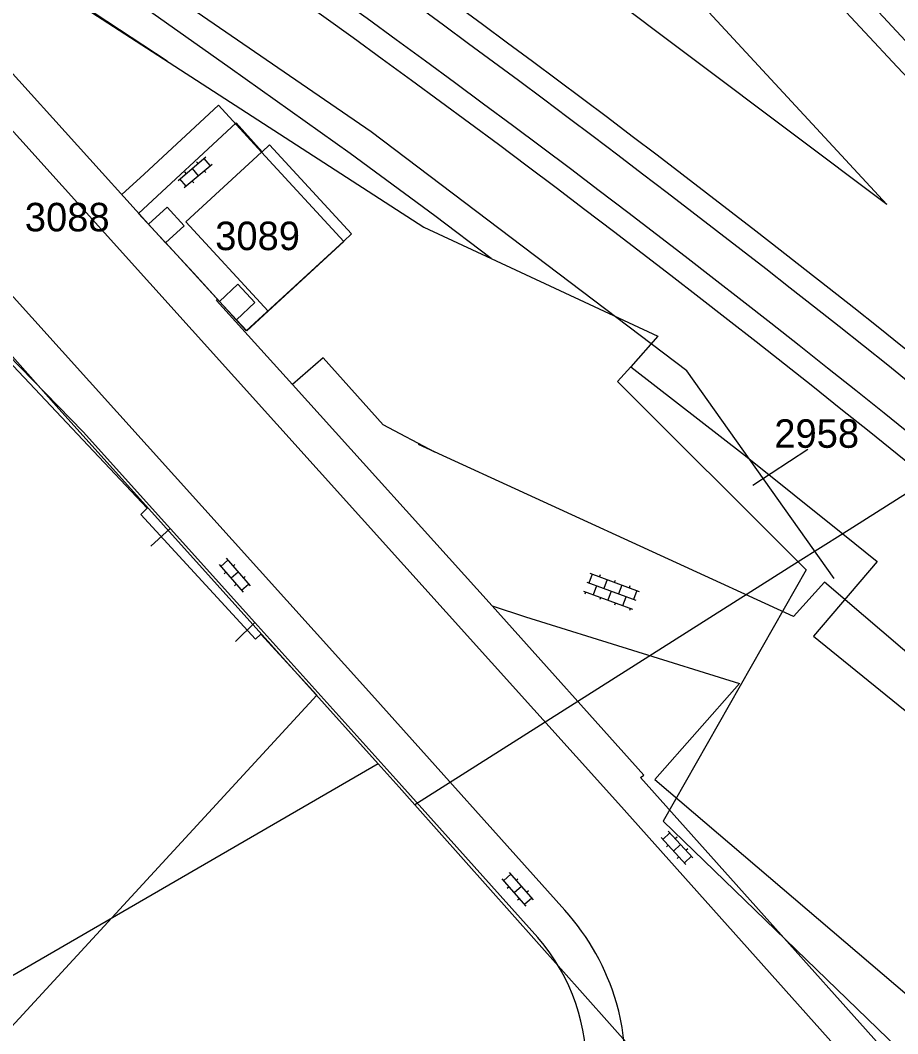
# Model space of a CAD drawing. Extents: x 148816 to 151297, y 399515 to 402500.
# Drawn here: x 149846 to 149901.4, y 399838.3 to 399902.3 of the extents above; entities that cross this region are included whole.
import ezdxf

# ---------------------------------------------------------------- set-up
doc = ezdxf.new("R2010")
doc.units = 0
for name, color, linetype in [('B01 Hoofdgebouw  [T] Norm', 7, 'Continuous'), ('B01 hoofgebouw', 7, 'Continuous'), ('G01 perceelsgrens', 7, 'Continuous'), ('Q01 Spoorrail  [D] Norm', 7, 'Continuous'), ('Q19 Overig lijnvormig object  [D] Gem', 7, 'Continuous'), ('S02 Open verharding  Norm', 7, 'Continuous'), ('T01 Muur  [T] Gem', 7, 'Continuous'), ('T04 Haag heg  [D] Gem', 7, 'Continuous'), ('V00 Kant verharding algemeen  [T] Norm', 7, 'Continuous'), ('Z01 perceelnummer', 7, 'Continuous')]:
    doc.layers.add(name, color=color, linetype=linetype)

msp = doc.modelspace()

# ---------------------------------------------------------------- linework, layer by layer
at = {"layer": 'B01 Hoofdgebouw  [T] Norm'}
msp.add_lwpolyline([(149866.456, 399888.377), (149861.68, 399883.975), (149856.48, 399889.615), (149861.256, 399894.018), (149866.456, 399888.377)], dxfattribs=at)
at = {"layer": 'B01 hoofgebouw'}
msp.add_lwpolyline([(149866.456, 399888.377), (149861.68, 399883.975), (149856.48, 399889.615), (149861.256, 399894.018), (149866.456, 399888.377)], dxfattribs=at)
at = {"layer": 'G01 perceelsgrens'}
for points in [[(149824.935, 399971.333), (149852.884, 399942.282), (149864.818, 399929.5), (149871.974, 399921.819), (149900.742, 399890.705), (149870.334, 399913.557), (149853.477, 399925.258), (149834.506, 399937.866), (149821.784, 399945.874), (149804.582, 399956.252), (149802.467, 399957.457)], [(149875.758, 399887.296), (149872.208, 399889.988), (149866.85, 399893.936), (149859.277, 399899.32), (149850.004, 399905.879), (149836.582, 399915.04), (149825.092, 399922.506), (149814.909, 399928.886), (149808.684, 399932.764), (149798.2, 399939.123), (149791.397, 399943.069)], [(149790.081, 399941.851), (149797.325, 399937.507), (149811.909, 399927.963), (149828.421, 399917.246), (149849.831, 399903.3), (149871.509, 399889.277), (149875.758, 399887.296)], [(149859.646, 399895.855), (149853.492, 399890.143)], [(149861.3, 399894.039), (149859.646, 399895.855)], [(149861.753, 399894.468), (149861.3, 399894.039)], [(149866.933, 399888.848), (149861.753, 399894.468)], [(149853.492, 399890.143), (149856.962, 399886.385)], [(149929.95, 399890.177), (149897.953, 399869.91)], [(149860.287, 399882.727), (149866.453, 399888.385)], [(149866.453, 399888.385), (149866.933, 399888.848)], [(149875.758, 399887.296), (149886.287, 399882.387), (149884.567, 399880.454)], [(149856.962, 399886.385), (149860.287, 399882.727)], [(149868.617, 399855.387), (149848.283, 399877.988), (149844.198, 399882.585)], [(149884.567, 399880.454), (149883.742, 399879.528), (149895.151, 399868.135)], [(149884.567, 399880.454), (149891.806, 399874.825), (149897.953, 399869.91)], [(149897.953, 399869.91), (149895.151, 399868.135)], [(149897.953, 399869.91), (149900.131, 399868.169), (149896.12, 399863.44), (149908.811, 399853.147), (149904.399, 399847.754), (149925.296, 399829.361), (149938.329, 399818.136), (149945.279, 399811.233), (149959.753, 399797.315), (149974.114, 399782.577), (149983.256, 399773.23), (149993.692, 399761.304), (150000, 399754.699)], [(149895.151, 399868.135), (149870.937, 399852.797)], [(149895.151, 399868.135), (149895.651, 399867.636), (149886.613, 399851.775), (149902.731, 399836.159), (149928.371, 399811.629), (149934.035, 399805.696), (149933.719, 399805.421)], [(149868.617, 399855.387), (149834.908, 399835.857), (149834.289, 399833.183)], [(149870.937, 399852.797), (149869.945, 399853.91), (149868.617, 399855.387)], [(149957.351, 399719.887), (149956.41, 399721.331), (149950.17, 399730.991), (149946.258, 399736.942), (149943.568, 399741.016), (149939.872, 399747.868), (149932.064, 399762.587), (149924.088, 399777.479), (149924.56, 399777.709), (149921.456, 399787.322), (149922.054, 399787.507), (149916.585, 399805.472), (149903.205, 399816.56), (149870.937, 399852.797)]]:
    msp.add_lwpolyline(points, dxfattribs=at)
at = {"layer": 'Q01 Spoorrail  [D] Norm'}
for p, q in [((149887.692, 399916.316), (149902.498, 399900.422)), ((149886.594, 399915.294), (149901.4, 399899.4)), ((149901.4, 399899.4), (149918.82, 399880.701))]:
    msp.add_line(p, q, dxfattribs=at)
for centre, radius, start, end in [((149374.899, 399222.566), 839.824, 47.976611, 67.901486), ((149374.91, 399222.59), 843.799, 50.163417, 67.241111), ((149374.899, 399222.566), 838.324, 47.976611, 67.901486), ((149374.91, 399222.59), 842.299, 50.163417, 67.241111), ((151998.933, 402054.677), 2999.25, 225.295789, 226.202153), ((151998.933, 402054.677), 3000.75, 225.295789, 226.202153)]:
    msp.add_arc(centre, radius, start, end, dxfattribs=at)
at = {"layer": 'Q19 Overig lijnvormig object  [D] Gem'}
for points in [[(149856.377, 399889.35), (149855.199, 399888.282), (149854.127, 399889.465), (149855.305, 399890.533), (149856.377, 399889.35)], [(149859.762, 399885.667), (149860.835, 399884.513), (149859.67, 399883.431), (149858.598, 399884.584), (149859.762, 399885.667)]]:
    msp.add_lwpolyline(points, dxfattribs=at)
at = {"layer": 'S02 Open verharding  Norm'}
for p, q in [((149855.992, 399892.227), (149857.748, 399893.713)), ((149857.155, 399893.407), (149857.252, 399893.293)), ((149858.021, 399893.158), (149857.634, 399893.616)), ((149856.38, 399891.769), (149858.136, 399893.255)), ((149856.392, 399892.762), (149856.489, 399892.647)), ((149856.87, 399892.97), (149857.258, 399892.512)), ((149857.639, 399892.835), (149857.736, 399892.72)), ((149856.494, 399891.866), (149856.107, 399892.324)), ((149856.876, 399892.189), (149856.973, 399892.075)), ((149858.579, 399867.97), (149860.086, 399866.233)), ((149858.677, 399867.857), (149859.13, 399868.25)), ((149859.032, 399868.363), (149860.539, 399866.626)), ((149859.571, 399867.971), (149859.458, 399867.872)), ((149859.005, 399867.479), (149858.891, 399867.381)), ((149859.786, 399867.495), (149859.332, 399867.101)), ((149860.227, 399867.215), (149860.113, 399867.117)), ((149882.138, 399867.366), (149881.93, 399866.803)), ((149881.997, 399867.418), (149885.094, 399866.278)), ((149882.607, 399867.194), (149882.659, 399867.334)), ((149859.66, 399866.724), (149859.547, 399866.625)), ((149859.988, 399866.346), (149860.441, 399866.739)), ((149881.79, 399866.855), (149884.886, 399865.715)), ((149882.4, 399866.631), (149882.192, 399866.068)), ((149883.076, 399867.021), (149882.869, 399866.458)), ((149883.545, 399866.848), (149883.597, 399866.989)), ((149884.015, 399866.675), (149883.807, 399866.112)), ((149884.484, 399866.502), (149884.536, 399866.643)), ((149881.582, 399866.292), (149884.679, 399865.152)), ((149881.723, 399866.24), (149881.671, 399866.1)), ((149882.661, 399865.895), (149882.61, 399865.754)), ((149883.338, 399866.285), (149883.131, 399865.722)), ((149884.069, 399865.376), (149884.276, 399865.939)), ((149884.953, 399866.33), (149884.746, 399865.767)), ((149883.6, 399865.549), (149883.548, 399865.408)), ((149884.538, 399865.204), (149884.486, 399865.063)), ((149886.941, 399851.134), (149888.498, 399849.441)), ((149886.5, 399850.727), (149888.057, 399849.034)), ((149886.601, 399850.617), (149887.043, 399851.023)), ((149887.492, 399850.757), (149887.381, 399850.655)), ((149886.94, 399850.249), (149886.829, 399850.147)), ((149887.72, 399850.287), (149887.278, 399849.881)), ((149888.169, 399850.021), (149888.058, 399849.919)), ((149887.617, 399849.513), (149887.506, 399849.411)), ((149887.955, 399849.145), (149888.397, 399849.551)), ((149877.97, 399846.399), (149876.455, 399848.129)), ((149877.005, 399848.412), (149876.553, 399848.017)), ((149878.421, 399846.795), (149876.906, 399848.525)), ((149877.334, 399848.036), (149877.447, 399848.135)), ((149876.77, 399847.542), (149876.883, 399847.64)), ((149877.212, 399847.264), (149877.664, 399847.66)), ((149877.993, 399847.284), (149878.106, 399847.382)), ((149877.429, 399846.789), (149877.542, 399846.888)), ((149878.323, 399846.907), (149877.871, 399846.512))]:
    msp.add_line(p, q, dxfattribs=at)
at = {"layer": 'T01 Muur  [T] Gem'}
msp.add_lwpolyline([(149897.414, 399867.088), (149888.109, 399880.201), (149868.176, 399895.284), (149825.163, 399924.795), (149797.931, 399941.546)], dxfattribs=at)
at = {"layer": 'T04 Haag heg  [D] Gem'}
msp.add_line((149829.036, 399917.103), (149855.288, 399899.781), dxfattribs=at)
for points in [[(149827.619, 399868.664), (149843.536, 399882.658), (149854.029, 399871.541), (149853.626, 399871.124), (149860.865, 399863.267)], [(149860.865, 399863.267), (149861.215, 399863.572), (149864.738, 399859.725)], [(149864.738, 399859.725), (149803.694, 399793.42), (149777.287, 399760.87), (149765.819, 399770.287), (149758.601, 399796.332), (149754.395, 399811.511)]]:
    msp.add_lwpolyline(points, dxfattribs=at)
at = {"layer": 'V00 Kant verharding algemeen  [T] Norm'}
for p, q in [((149894.84, 399864.69), (149871.164, 399875.541)), ((149896.81, 399866.86), (149894.84, 399864.69)), ((149912.78, 399853.17), (149896.81, 399866.86)), ((149877.93, 399864.66), (149891.43, 399860.46)), ((149891.43, 399860.46), (149886.09, 399854.4)), ((149886.09, 399854.4), (149924.26, 399821.79))]:
    msp.add_line(p, q, dxfattribs=at)
for points in [[(149783.867, 399930.153), (149801.807, 399917.51), (149806.491, 399913.379), (149820.183, 399903.213), (149820.536, 399903.043), (149826.3, 399901.511), (149826.5, 399901.56), (149826.945, 399901.133), (149826.786, 399900.967), (149831.874, 399896.283), (149832.042, 399896.284), (149832.473, 399895.84), (149832.329, 399895.701), (149836.497, 399891.519), (149843.98, 399883.178), (149843.647, 399882.865), (149849.997, 399876.354), (149860.836, 399864.314), (149870.121, 399853.988)], [(149854.127, 399889.465), (149845.146, 399899.395)], [(149883.79, 399852.872), (149843.3, 399897.825)], [(149853.837, 399892.621), (149858.531, 399896.971), (149861.256, 399894.018)], [(149837.904, 399893.349), (149868.213, 399859.744)], [(149853.837, 399892.621), (149852.434, 399891.337)], [(149858.598, 399884.584), (149855.209, 399888.291)], [(149872.194, 399875.069), (149868.929, 399876.802), (149865.148, 399881.019), (149863.208, 399879.343), (149858.41, 399884.654), (149858.472, 399884.721)], [(149861.68, 399883.975), (149860.321, 399882.731), (149859.67, 399883.431)], [(149875.829, 399865.355), (149863.208, 399879.343)], [(149854.256, 399869.137), (149855.492, 399870.25)], [(149885.191, 399854.517), (149885.396, 399854.671), (149875.829, 399865.355), (149877.93, 399864.66)], [(149860.836, 399864.314), (149859.613, 399863.103)], [(149868.213, 399859.744), (149880.412, 399846.152)], [(149908.436, 399828.513), (149885.191, 399854.517)], [(149870.121, 399853.988), (149878.707, 399844.415)], [(149907.091, 399826.801), (149883.79, 399852.872)]]:
    msp.add_lwpolyline(points, dxfattribs=at)
for centre, radius, start, end in [((149868.876, 399835.879), 15.447, 16.59239, 41.68597), ((149869.17, 399836.169), 12.608, 314.62071, 40.84989), ((149869.022, 399836.245), 15.206, 312.98741, 15.42736)]:
    msp.add_arc(centre, radius, start, end, dxfattribs=at)
at = {"layer": 'Z01 perceelnummer'}
msp.add_lwpolyline([(149895.756, 399875.242), (149892.285, 399872.955)], dxfattribs=at)

# ---------------------------------------------------------------- texts
for s, p in [('3088', (149846.309, 399889.01)), ('3089', (149858.33, 399887.824)), ('2958', (149893.634, 399875.342))]:
    msp.add_text(s, height=1.8, dxfattribs=at).set_placement(p)

doc.saveas('drawing.dxf')
